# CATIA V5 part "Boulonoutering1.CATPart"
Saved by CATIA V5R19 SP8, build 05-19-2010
Part number: Boulonoutering1
Bounding box of the stored display mesh (mm): x -8 to 8, y 442 to 458, z 722 to 774
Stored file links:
  G:\EU_thinkMotion\CFAO_2010\MMS_groupe3\MMS_groupe3\A reprendre\fovide\fovide\Boulonoutering1.CATPart
  C:\Users\Rodger\Desktop\Part11.CATPart
  G:\EU_thinkMotion\CFAO_2010\MMS_groupe3\MMS_groupe3\A reprendre\fovide\fovide\fovide.CATProduct
  G:\EU_thinkMotion\CFAO_2010\MMS_groupe3\MMS_groupe3\A reprendre\fovide\fovide\Outering Segment 6a.CATPart
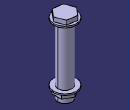
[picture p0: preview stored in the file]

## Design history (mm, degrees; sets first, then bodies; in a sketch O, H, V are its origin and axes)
Parameters
  Diametre = 10 mm
  Longueur = 40 mm
Set1
  DatumSurface1: linked copy from another document
  Point1: linked copy from another document
Body1 (main body)
Body2
  Sketch1 on DatumSurface1, origin (0, 0, 770), H (1, 0, 0), V (0, 1, 0)
    circle A1 centre (0, 450) radius 8
    point P1 (0, 450)
    reference projected point E1 (0, 450) from Point1
    radius A1 = 8 {= Diametre *8/10}
    coincidence: P1 E1
  Pad1: profile Sketch1, direction (0, 0, 1), length 1
  Sketch2 on end face of Pad1, origin (0, 0, 771), H (1, 0, 0), V (0, 1, 0)
    point P1 (0, 450)
    point P2 (2.4939, 443.4593)
    point P3 (6.9113, 448.8894)
    point P4 (4.4175, 455.4301)
    point P5 (-2.4939, 456.5407)
    point P6 (-6.9113, 451.1106)
    point P7 (-4.4175, 444.5699)
    point P8 (4.7026, 446.1744)
    line L1 (2.4939, 443.4593) -> (6.9113, 448.8894)
    line L2 (6.9113, 448.8894) -> (4.4175, 455.4301)
    line L3 (4.4175, 455.4301) -> (-2.4939, 456.5407)
    line L4 (-2.4939, 456.5407) -> (-6.9113, 451.1106)
    line L5 (-6.9113, 451.1106) -> (-4.4175, 444.5699)
    line L6 (-4.4175, 444.5699) -> (2.4939, 443.4593)
    construction line L7 (0, 450) -> (4.7026, 446.1744)
    construction circle A1 centre (0, 450) radius 7
    construction arc A2 centre (-6.9113, 451.1106) radius 7 from (-2.4939, 456.5407) to (-4.4175, 444.5699) cw
    construction arc A3 centre (6.9113, 448.8894) radius 7 from (4.4175, 455.4301) to (2.4939, 443.4593) ccw
    reference projected point E1 (0, 450) from Point1
    radius A1 = 7 {= Diametre *7/10}
    coincidence: A1 P2, A1 P3, A1 P4, A1 P5, A1 P6, A1 P7, A2 P1, A3 P1, P1 E1
    midpoint: P8 L1
    parallelism: L1 L4
  Pad2: profile Sketch2, direction (0, 0, 1), length 3
  Sketch3 on start face of Pad1, origin (0, 0, 770), H (1, 0, 0), V (0, -1, 0)
    circle A1 centre (0, -450) radius 5
    point P1 (0, -450)
    reference projected point E1 (0, -450) from Point1
    radius A1 = 5 {= Diametre /2}
    coincidence: P1 E1
  Pad3: profile Sketch3, direction (0, 0, -1), length 40 {= Longueur}
  Sketch4 on end face of Pad3, origin (0, 0, 730), H (1, 0, 0), V (0, -1, 0)
    circle A1 centre (0, -450) radius 8
    point P1 (0, -450)
    reference projected point E1 (0, -450) from Point1
    radius A1 = 8 {= Diametre *8/10}
    coincidence: P1 E1
  Pad4: profile Sketch4, direction (0, 0, -1), length 1
  Sketch5 on end face of Pad4, origin (0, 0, 729), H (1, 0, 0), V (0, -1, 0)
    point P1 (0, -450)
    point P2 (-0.0478, -456.9998)
    point P3 (6.0381, -453.5413)
    point P4 (6.0859, -446.5415)
    point P5 (0.0478, -443.0002)
    point P6 (-6.0381, -446.4587)
    point P7 (-6.0859, -453.4585)
    point P8 (2.9952, -455.2706)
    line L1 (-0.0478, -456.9998) -> (6.0381, -453.5413)
    line L2 (6.0381, -453.5413) -> (6.0859, -446.5415)
    line L3 (6.0859, -446.5415) -> (0.0478, -443.0002)
    line L4 (0.0478, -443.0002) -> (-6.0381, -446.4587)
    line L5 (-6.0381, -446.4587) -> (-6.0859, -453.4585)
    line L6 (-6.0859, -453.4585) -> (-0.0478, -456.9998)
    construction line L7 (0, -450) -> (2.9952, -455.2706)
    construction circle A1 centre (0, -450) radius 7
    construction arc A2 centre (-6.0381, -446.4587) radius 7 from (0.0478, -443.0002) to (-6.0859, -453.4585) cw
    construction arc A3 centre (6.0381, -453.5413) radius 7 from (6.0859, -446.5415) to (-0.0478, -456.9998) ccw
    reference projected point E1 (0, -450) from Point1
    radius A1 = 7 {= Diametre *7/10}
    coincidence: A1 P2, A1 P3, A1 P4, A1 P5, A1 P6, A1 P7, A2 P1, A3 P1, P1 E1
    midpoint: P8 L1
    parallelism: L1 L4
  Pad5: profile Sketch5, direction (0, 0, -1), length 3
  Sketch6 on end face of Pad5, origin (0, 0, 726), H (1, 0, 0), V (0, -1, 0)
    circle A1 centre (0, -450) radius 5
    point P1 (0, -450)
    reference projected point E1 (0, -450) from Point1
    radius A1 = 5 {= Diametre /2}
    coincidence: P1 E1
  Pad6: profile Sketch6, direction (0, 0, -1), length 4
